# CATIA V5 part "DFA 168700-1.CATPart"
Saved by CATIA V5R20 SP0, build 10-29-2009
Part number: DFA 168700-1
Revision: ANY
Definition: UNKNOWN
Nomenclature: DFA 168700-1
Source: Unknown
Bounding box of the stored display mesh (mm): x -3.804 to 3.804, y 0.28 to 2.5, z -4 to 4
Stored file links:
  C:\Users\Utente\Desktop\IO LAVORO\3D X SITO CF\CUMSA\3D files FA\FA 168712-21\DFA 168700-1.CATPart
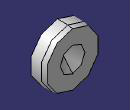
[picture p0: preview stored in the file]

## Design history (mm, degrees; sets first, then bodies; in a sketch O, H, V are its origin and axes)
Body1 "Cortar-Extruir1" (main body)
  Solid1: solid without history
